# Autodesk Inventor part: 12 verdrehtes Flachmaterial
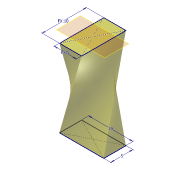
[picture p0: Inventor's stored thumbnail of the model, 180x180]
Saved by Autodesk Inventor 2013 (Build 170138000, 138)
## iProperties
Created: 2012-10
Part Number: 12 verdrehtes Flachmaterial
Material: Allgemein
Document SubType Name: Modeling
Designer: Administrator
Density: 1 g/cm^3
Author: Administrator
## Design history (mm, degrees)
sketch "Skizze1"
  geometry: L1 (-5, -2.5)-(5, -2.5); L2 (5, -2.5)-(5, 2.5); L3 (5, 2.5)-(-5, 2.5); L4 (-5, 2.5)-(-5, -2.5); L5 (-5, -2.5)-(5, 2.5); L6 (5, -2.5)-(-5, 2.5); 1 further point
  constraints: 12 end point, 2 midpoint, 2 parallel, 1 horizontal, 1 perpendicular
  dimensions: "d0" = 10 distance of L3.end L2.end; "d1" = 5 distance of L2.end L1.end
workplane "Arbeitsebene1"
sketch "Skizze2"
  geometry: L1 (-2.5, 5)-(2.5, 5); L2 (2.5, 5)-(2.5, -5); L3 (2.5, -5)-(-2.5, -5); L4 (-2.5, -5)-(-2.5, 5); L5 (-2.5, 5)-(2.5, -5); L6 (2.5, 5)-(-2.5, -5); 1 further point
  constraints: 12 end point, 2 midpoint, 2 parallel, 1 horizontal, 1 perpendicular
  dimensions: "d3" = 5 distance of L2.end L3.end (= d1); "d5" = 10 distance of L3.end L1.start (= d0)
feature "Erhebung1" sketch "Skizze2" dims "d6" = 0, "d7" = 90 deg, "d8" = 0, "d9" = 90 deg
node "Volumenkörper1"
